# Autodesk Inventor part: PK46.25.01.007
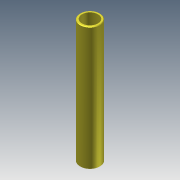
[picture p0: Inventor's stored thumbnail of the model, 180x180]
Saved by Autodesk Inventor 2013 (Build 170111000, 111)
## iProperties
Created: 2005-04
Part Number: PK46.25.01.007
Material: Steel, Mild
Document SubType Name: Modeling
Designer: salex
Manufacturer: Standard
Standards Organization: Custom
Density: 7.86 g/cm^3
Mass: 55305.7 g
Surface Area: 8925.19 cm^2
Volume: 7036.35 cm^3
Author: salex
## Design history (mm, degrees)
sketch "Эскиз1"
  geometry: C1 r 63.5 at (0, 0); C2 r 79.5 at (0, 0)
  constraints: 2 centre point, 1 coincident, 1 other
  dimensions: "d0" = 159 diameter of C2; "d1" = 127 diameter of C1
extrude "Выдавливание1" new body sketch "Эскиз1" distance "d2" = 980; taper "d3" = 0 deg
chamfer "Фаска1" distance "d4" = 4; stored, may be unused: second distance "d5" = 2, angle "d6" = 45 deg
body "Solid1"
